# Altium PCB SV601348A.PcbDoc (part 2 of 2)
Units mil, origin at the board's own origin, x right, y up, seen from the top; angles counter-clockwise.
Board outline 3650 x 3650 mil, 6 copper layers (Top Layer, MidLayer1, MidLayer2, MidLayer3, MidLayer4, Bottom Layer), stack 60.8 mil thick; 120 components, 45 nets, 333 pads, 436 vias.
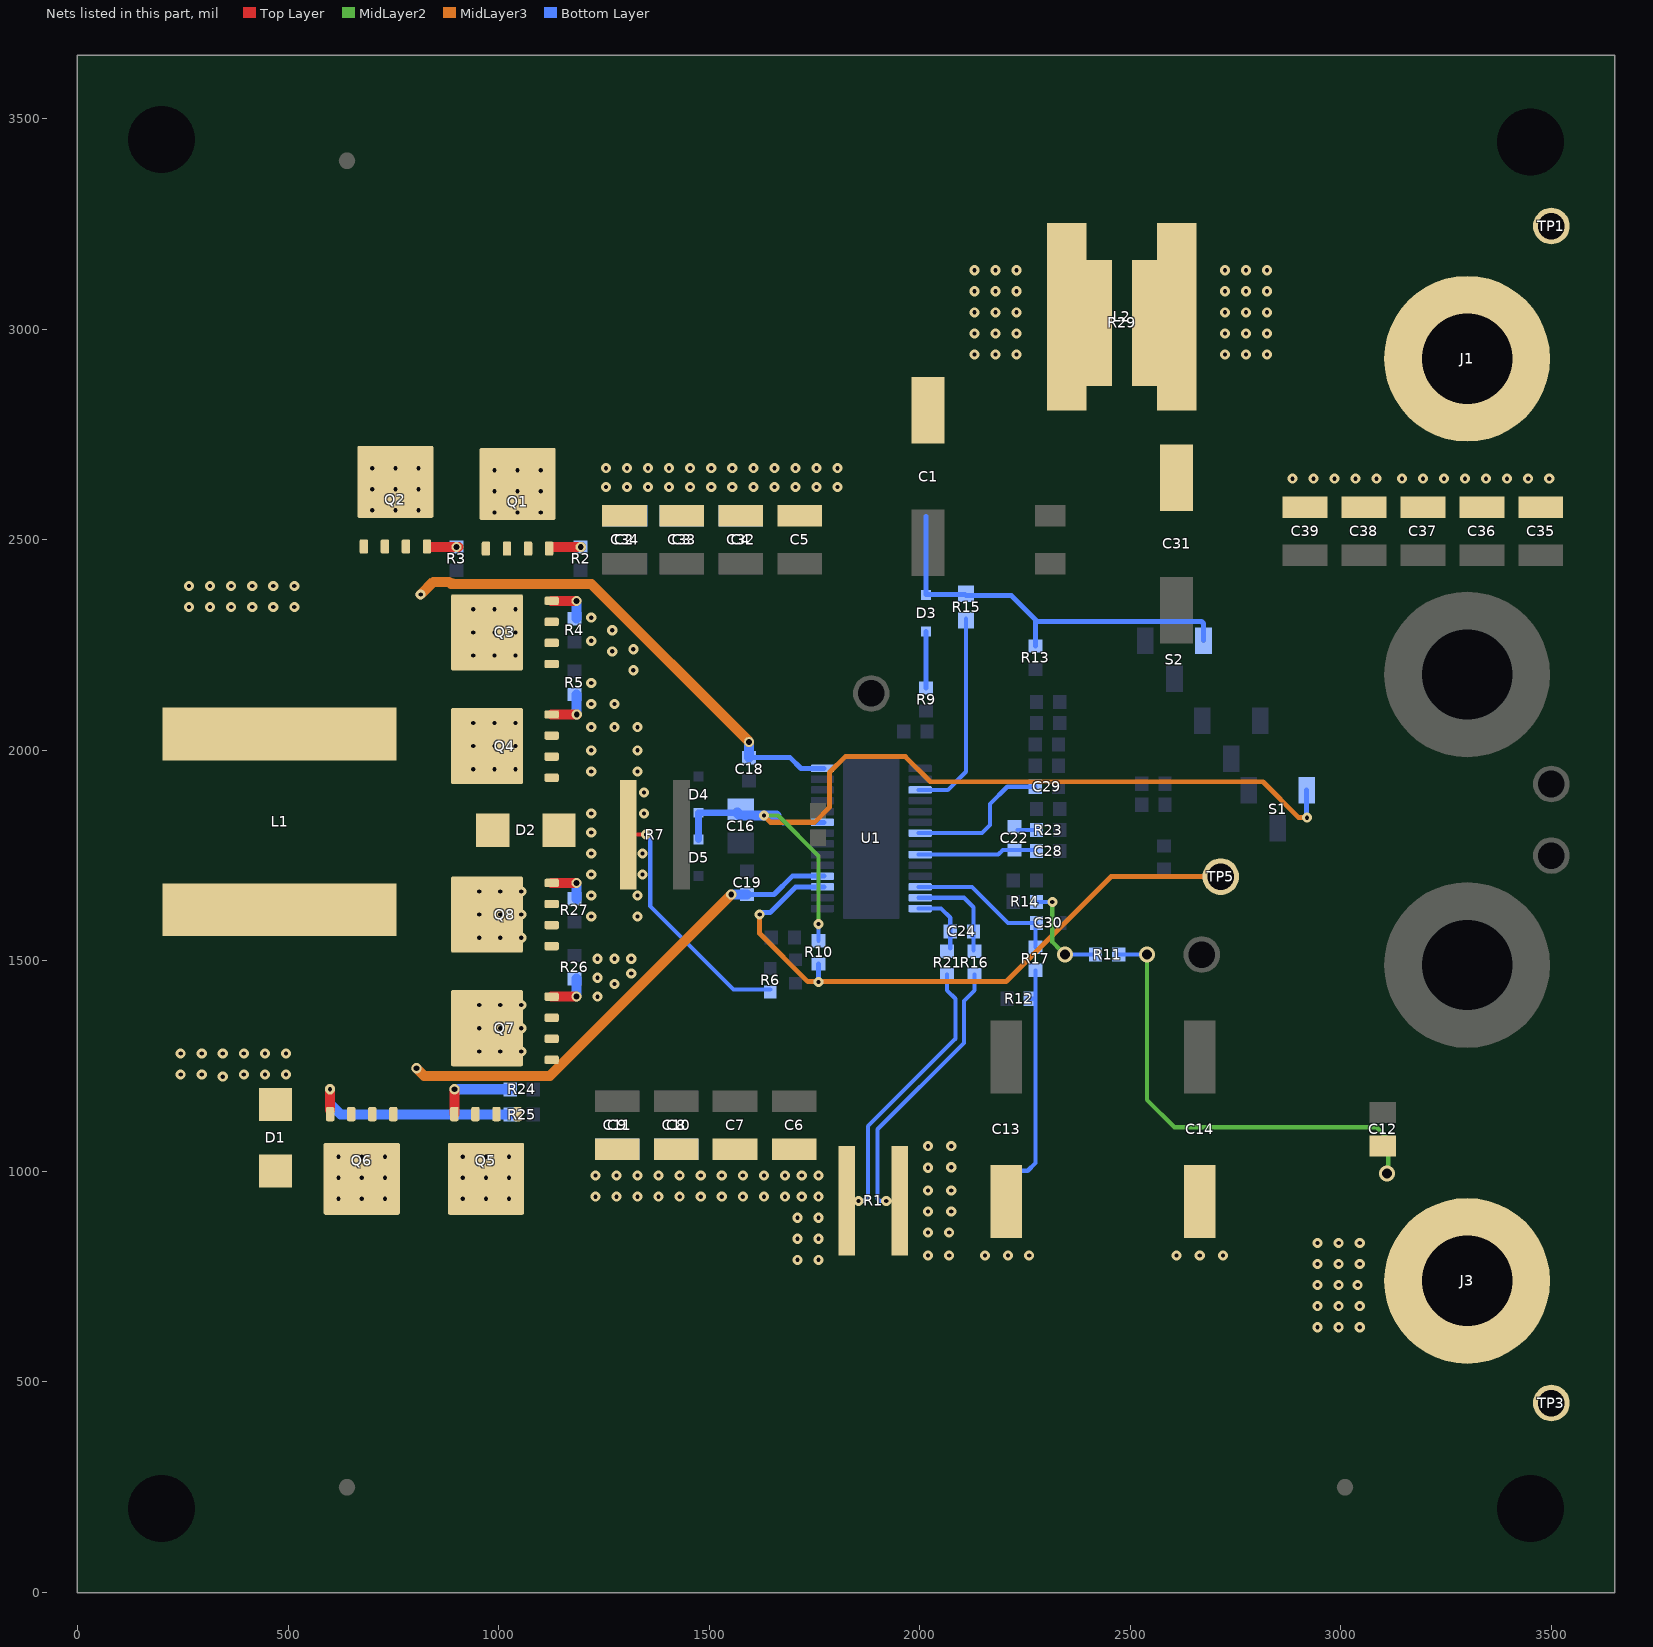
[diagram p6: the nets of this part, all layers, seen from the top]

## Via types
v1: diameter 24, hole 10, Top Layer to Bottom Layer, tented both sides, 317 vias
v2: diameter 24, hole 10, Top Layer to Bottom Layer, 74 vias
v3: diameter 19.68, hole 7.87, Top Layer to Bottom Layer, tented both sides, 12 vias
v4: diameter 24, hole 14, Top Layer to Bottom Layer, 11 vias
v5: diameter 19.68, hole 7.87, Top Layer to Bottom Layer, 9 vias
v6: diameter 24, hole 14, Top Layer to Bottom Layer, tented both sides, 8 vias
v7: diameter 24, hole 10, Top Layer to Bottom Layer, tented top, 2 vias
v8: diameter 38, hole 24, Top Layer to Bottom Layer, 2 vias
v9: diameter 38, hole 24, Top Layer to Bottom Layer, tented both sides, 1 vias

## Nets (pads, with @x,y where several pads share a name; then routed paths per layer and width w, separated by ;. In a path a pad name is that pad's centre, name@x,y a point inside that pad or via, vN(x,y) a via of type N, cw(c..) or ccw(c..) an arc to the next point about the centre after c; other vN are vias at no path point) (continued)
NetC22_1: C22.1 C28.1 U1.9 | length 282.3
  Bottom Layer w10: U1.9@1997.2,1752.24 2186.61,1752.24 2197.44,1763.07 C22.1@2225,1763.07 C28.1@2275,1763.07
NetC22_2: C22.2 R23.2 | length 44.9
  Bottom Layer w10: C22.2@2232.56,1810.63 R23.2@2277.44,1810.63
NetC24_1: C24.1 R16.1 U1.13 | length 242.1
  Bottom Layer w10: U1.13@1997.2,1649.88 2105.12,1649.88 2127.56,1627.44 C24.1@2127.56,1570 R16.1@2127.56,1525
NetC24_2: C24.2 R21.1 U1.14 | length 156.8
  Bottom Layer w10: U1.14@1997.2,1624.29 2050.71,1624.29 2072.44,1602.56 C24.2@2072.44,1570 R21.1@2072.44,1530
NetC29_1: C29.1 U1.7 | length 352.3
  Bottom Layer w10: U1.7@1997.2,1803.43 2147.8,1803.43 2167.13,1822.76 2167.13,1872.76 2207.8,1913.43 C29.1@2274.64,1913.43
NetC31_1: C31.1 C35.1 C36.1 C37.1 C38.1 C39.1 J1.1 L2.1 R29.1 TP1.1
  other v1: 2885,2645 2935,2645 2985,2645 3035,2645 3085,2645 3145,2645 3195,2645 3245,2645 3295,2645 3345,2645 3395,2645 3445,2645 3495,2645 2725,2940 2775,2940 2825,2940 2725,2990 2775,2990 2825,2990 2725,3040 2775,3040 2825,3040 2725,3090 2775,3090 2825,3090 2725,3140 2775,3140 2825,3140
NetD2_2: D2.2 Q3.1 Q3.2 Q3.3 Q4.1 Q4.2 Q4.3 Q7.1 Q7.2 Q7.3 Q8.1 Q8.2 Q8.3 R6.2 R7.2 | length 583
  Top Layer w10: R7.2@1308.37,1799.47 1308.9,1800 v1(1350,1800)
  Bottom Layer w10: v1(1350,1800) 1360,1790 1360,1630 1558,1432 R6.2@1645,1432
  other v1: 1235,1415 1275,1445 1235,1460 1315,1470 1235,1505 1275,1505 1315,1505 1220,1605 1330,1605 1220,1655 1330,1655 1220,1705 1342,1705 1220,1755 1342,1755 1220,1805 1220,1850 1345,1850 1345,1900 1220,1950 1330,1950 1220,2000 1330,2000 1220,2055 1275,2055 1330,2055 1220,2110 1275,2110 1220,2160 1320,2190 1270,2235 1320,2240 1220,2260 1270,2285 1220,2315
NetD3_1: D3.1 R9.2 | length 133.5
  Bottom Layer w12: R9.2@2015,2148.19 D3.1@2015,2281.69
NetQ1_4: Q1.4 R2.1 | length 70.7
  Top Layer w24: Q1.4@1124.27,2483.05 v4(1195,2483.05)
NetQ2_4: Q2.4 R3.1 | length 68.8
  Top Layer w24: Q2.4@836.22,2482.56 v4(900,2482.56) v4@905,2482.56
NetQ3_4: Q3.4 R4.1 | length 101.2
  Top Layer w24: Q3.4@1126.22,2355 v4(1185,2355)
  Bottom Layer w24: R4.1@1185,2312.56 v4(1185,2355)
NetQ4_4: Q4.4 R5.1 | length 106.2
  Top Layer w24: Q4.4@1126.22,2085 v4(1185.55,2085)
  Bottom Layer w24: v4@1185,2085.55 R5.1@1185,2132.44
NetQ5_4: Q5.4 R24.1 | length 191.2
  Top Layer w24: Q5.4@895,1136.22 v4(895,1195)
  Bottom Layer w24: v4(895,1195) R24.1@1027.44,1195
NetQ6_4: Q6.4 R25.1 | length 521.6
  Top Layer w24: Q6.4@600,1146.22 v2(600,1195)
  Bottom Layer w24: v2(600,1195) 600,1160 625,1135 R25.1@1027.44,1135
NetQ7_4: Q7.4 R26.1 | length 101.2
  Top Layer w24: Q7.4@1126.22,1415 v4(1185,1415)
  Bottom Layer w24: v4(1185,1415) R26.1@1185,1457.44
NetQ8_4: Q8.4 R27.1 | length 96.2
  Top Layer w24: Q8.4@1126.22,1685 v4(1185,1685)
  Bottom Layer w24: R27.1@1185,1647.56 v4(1185,1685)
NetR10_1: R10.1 TP5.1 U1.17 | length 1513.1
  MidLayer3 w12: v1(1620,1610) 1620,1565 1734.36,1450.64 2205.08,1450.64 2454.45,1700 TP5.1@2715,1700 TP5.1@2715.13,1700
  Bottom Layer w12: v1(1620,1610) 1625,1615 1645,1615 1705.47,1675.47 U1.17@1772.8,1675.47 ; v1(1760,1450) R10.1@1760,1492.44
NetR11_2: R11.2 R14.2 | length 228.2
  MidLayer2 w10: v7(2315,1640) 2315,1545 v8@2335,1525
  Bottom Layer w10: R14.2@2277.56,1640 v7(2315,1640) ; v8(2345,1515) R11.2@2412.44,1515
NetR15_1: R15.1 U1.3 | length 494.2
  Bottom Layer w10: U1.3@1997.2,1905.79 2066.85,1905.79 2110,1948.94 R15.1@2110,2312.44
SW1: C18.1 D2.1 L1.1 Q1.1 Q1.2 Q1.3 Q2.1 Q2.2 Q2.3 Q3.5 Q3.6 Q3.7 Q3.8 Q3.9@972.48,2280 Q4.5 Q4.6 Q4.7 Q4.8 Q4.9@972.48,2010 U1.28 | length 1175.7
  MidLayer3 w24: v2(815,2370) 845,2400 882.36,2400 886.8,2395.57 891.3,2395.57 891.8,2395.07 1219.93,2395.07 v6(1595,2020)
  Bottom Layer w12: C18.1@1595,1982.56 1692.44,1982.56 1718.03,1956.97 U1.28@1772.8,1956.97
  Bottom Layer w24: C18.1@1595,1982.56 v6(1595,2020)
  other v1: 265,2340 315,2340 365,2340 415,2340 465,2340 515,2340 265,2390 315,2390 365,2390 415,2390 465,2390 515,2390
  other v2: 940,1955 990,1955 1040,1955 940,2010 990,2010 1040,2010 940,2065 990,2065 1040,2065 940,2225 990,2225 1040,2225 940,2280 990,2280 1040,2280 940,2335 990,2335 1040,2335
SW2: C19.2 D1.2 L1.2 Q5.1 Q5.2 Q5.3 Q6.1 Q6.2 Q6.3 Q7.5 Q7.6 Q7.7 Q7.8 Q7.9@972.48,1340 Q8.5 Q8.6 Q8.7 Q8.8 Q8.9@972.48,1610 U1.18 | length 1171.7
  MidLayer3 w24: v4(805,1245) 823.13,1226.87 1121.87,1226.87 v6(1552.44,1657.44)
  Bottom Layer w12: C19.2@1590,1657.44 1654.03,1657.44 1697.65,1701.06 U1.18@1772.8,1701.06
  Bottom Layer w24: v6(1552.44,1657.44) C19.2@1590,1657.44
  other v1: 345,1225 245,1230 295,1230 395,1230 445,1230 495,1230 245,1280 295,1280 345,1280 395,1280 445,1280 495,1280
  other v2: 954,1285 1004,1285 1054,1285 954,1340 1004,1340 1054,1340 954,1395 1004,1395 1054,1395 954,1555 1004,1555 1054,1555 954,1610 1004,1610 1054,1610 954,1665 1004,1665 1054,1665
VCC: C16.2 D4.2 D5.2 R10.2 S1.3 U1.23 | length 2275.6
  MidLayer2 w10: v1(1630,1845) 1664.13,1845 1760,1749.13 v1(1760,1587.87) v1@1760,1580
  MidLayer3 w12: v1(1630,1845) 1645.87,1829.13 1750.47,1829.13 1785.88,1864.54 1785.88,1947.6 1823.29,1985 1965.8,1985 2025,1925.8 2815,1925 2900,1840 v1(2920,1840)
  Bottom Layer w10: R10.2@1760,1547.56 v1@1760,1580
  Bottom Layer w12: 1675.98,1829.02 U1.23@1768.86,1829.02 U1.23@1772.8,1829.02 ; v1@2918.9,1841.1 S1.3@2918.9,1905.28
  Bottom Layer w16: D5.2@1475,1788.31 D4.2@1475,1851.69 C16.2@1566.69,1851.69 ; 1659.41,1845.59 1675.98,1829.02
  Bottom Layer w24: C16.2@1566.69,1851.69 1572.79,1845.59 1659.41,1845.59
VIN: C1.1 C2.1 C3.1 C4.1 C5.1 C32.1 C33.1 C34.1 D3.2 L2.2 Q1.5 Q1.6 Q1.7 Q1.8 Q1.9@1045,2632.52 Q2.5 Q2.6 Q2.7 Q2.8 Q2.9@755,2637.52 R13.2 R15.2 R29.2 S2.3 | length 973.3
  Bottom Layer w12: 2015,2555 2015,2369.47 R15.2@2108.09,2369.47 ; R15.2@2110,2367.56 2217.44,2367.56 2275,2310 ; R13.2@2275,2247.56 2275,2250 2275,2310 ; S2.3@2673.9,2260.28 2673.9,2301.1 2669.35,2305.65 2279.35,2305.65 2275,2310
  other v1: 1255,2625 1305,2625 1355,2625 1405,2625 1455,2625 1505,2625 1555,2625 1605,2625 1655,2625 1705,2625 1755,2625 1805,2625 1255,2670 1305,2670 1355,2670 1405,2670 1455,2670 1505,2670 1555,2670 1605,2670 1655,2670 1705,2670 1755,2670 1805,2670 2130,2940 2180,2940 2230,2940 2130,2990 2180,2990 2230,2990 2130,3040 2180,3040 2230,3040 2130,3090 2180,3090 2230,3090 2130,3140 2180,3140 2230,3140
  other v2: 990,2565 1045,2565 1100,2565 700,2570 755,2570 810,2570 990,2615 1045,2615 1100,2615 700,2620 755,2620 810,2620 990,2665 1045,2665 1100,2665 700,2670 755,2670 810,2670
VOSNS: C30.1 R17.2 U1.12 | length 370.6
  Bottom Layer w10: U1.12@1997.2,1675.47 2124.53,1675.47 2210,1590 C30.1@2277.44,1590 ; R17.2@2275,1532.56 C30.1@2275,1587.56
VOSNS+: C6.1 C7.1 C8.1 C9.1 C10.1 C11.1 D1.1 Q5.5 Q5.6 Q5.7 Q5.8 Q5.9@970,982.48 Q6.5 Q6.6 Q6.7 Q6.8 Q6.9@675,982.48 R1.1 R21.2 | length 648.1
  Bottom Layer w10: v1(1855,930) 1867.13,930 1877.13,940 1877.13,1107.4 2085,1315.28 2085,1410 2065,1430 R21.2@2065,1467.44
  other v1: 1710,790 1760,790 1710,840 1760,840 1710,890 1760,890 1230,940 1280,940 1330,940 1380,940 1430,940 1480,940 1530,940 1580,940 1630,940 1680,940 1720,940 1760,940 1230,990 1280,990 1330,990 1380,990 1430,990 1480,990 1530,990 1580,990 1630,990 1680,990 1720,990 1760,990
  other v2: 620,935 675,935 730,935 915,935 970,935 1025,935 620,985 675,985 730,985 915,985 970,985 1025,985 620,1035 675,1035 730,1035 915,1035 970,1035 1025,1035
VOSNS-: C12.1 C13.1 C14.1 J3.1 R1.2 R11.1 R12.1 R16.2 R17.1 TP3.1 | length 2300.6
  MidLayer2 w10: v8(2540,1515) 2540,1170 2605,1105 3085,1105 3112.5,1077.5 v9@3112.5,997.5
  Bottom Layer w10: v1(1920.51,930) 1905,930 1900,935 1900,1100 2105,1305 2105,1405 2130,1430 R16.2@2130,1467.44 ; 2210,1001.57 2256.57,1001.57 2275,1020 R12.1@2275,1410 ; R12.1@2262.56,1410 R12.1@2275,1410 ; R17.1@2275,1477.44 R12.1@2275,1410 ; R11.1@2468.05,1515 R11.1@2472.56,1515 v8(2540,1515)
  other v1: 2945,630 2995,630 3045,630 2945,680 2995,680 3045,680 2945,730 2995,730 3040,730 2945,780 2995,780 3045,780 2020,800 2070,800 2155,800 2210,800 2260,800 2610,800 2665,800 2720,800 2945,830 2995,830 3045,830 2020,855 2070,855 2020,905 2075,905 2020,955 2075,955 2019.64,1008.59 2075,1010 2020,1060 2075,1060
  other v9: 3110,995
pads on no net: FID1.1 FID2.1 FID3.1 H5.0 H6.0 H7.0 H8.0 LBL1.0 MH1.1 MH2.1 MH3.1 MH4.1 Q1.9@987.13,2582.91 Q1.9@987.13,2649.06 Q1.9@1045,2582.91 Q1.9@1045,2649.06 Q1.9@1102.87,2582.91 Q1.9@1102.87,2649.06 Q2.9@697.13,2587.91 Q2.9@697.13,2654.06 Q2.9@755,2587.91 Q2.9@755,2654.06 Q2.9@812.87,2587.91 Q2.9@812.87,2654.06 Q3.9@955.94,2222.13 Q3.9@955.94,2280 Q3.9@955.94,2337.87 Q3.9@1022.09,2222.13 Q3.9@1022.09,2280 Q3.9@1022.09,2337.87 Q4.9@955.94,1952.13 Q4.9@955.94,2010 Q4.9@955.94,2067.87 Q4.9@1022.09,1952.13 Q4.9@1022.09,2010 Q4.9@1022.09,2067.87 Q5.9@912.13,965.94 Q5.9@912.13,1032.09 Q5.9@970,965.94 Q5.9@970,1032.09 Q5.9@1027.87,965.94 Q5.9@1027.87,1032.09 Q6.9@617.13,965.94 Q6.9@617.13,1032.09 Q6.9@675,965.94 Q6.9@675,1032.09 Q6.9@732.87,965.94 Q6.9@732.87,1032.09 Q7.9@955.94,1282.13 Q7.9@955.94,1340 Q7.9@955.94,1397.87 Q7.9@1022.09,1282.13 Q7.9@1022.09,1340 Q7.9@1022.09,1397.87 Q8.9@955.94,1552.13 Q8.9@955.94,1610 Q8.9@955.94,1667.87 Q8.9@1022.09,1552.13 Q8.9@1022.09,1610 Q8.9@1022.09,1667.87 S3.3 U1.29@1885,1790.63

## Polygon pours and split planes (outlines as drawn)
GND on MidLayer3 "Top Layer-No Net 6" (solid, remove dead copper, pour order 69): 0,15 0,3650 3650,3650 3650,15
GND on MidLayer4 "Top Layer-No Net 6" (solid, remove dead copper, pour order 70): 0,20 0,3650 3630,3650 3630,20
GND on MidLayer1 "Top Layer-No Net 6" (solid, remove dead copper, pour order 61): 0,20 0,3630 3630,3630 3630,20
GND on MidLayer2 "M4 3D STEP Bottom-No Net" (solid, remove dead copper, pour order 68): 1215.67,2500 3565,2500 3650,2415 3650,1955 3550,1855 3150.67,1855 3150.67,1825 3555,1825 3650,1730 3650,1105 1195.67,1105 1195.67,1195 1375.64,1374.97 1375.64,1524.4 1377.24,1800 1375.71,2065.59 1375.67,2245 1215.67,2405
SW2 on MidLayer2 "Top Layer-No Net 3" (solid, remove dead copper, pour order 63): 1085.08,1110 285,1110 195,1200 195,1640 720,1640 815,1735 1079.88,1735
SW1 on MidLayer2 "Top Layer-No Net 4" (solid, remove dead copper, pour order 64): 1080,1765 1080,2510 265.4,2510 194.3,2439.6 192.24,2233.86 192.24,1990 715,1990 940,1765
NetD2_2 on MidLayer2 "Top Overlay-No Net" (solid, remove dead copper, pour order 62): 1102.7,1221.89 1104.59,1220 1195,1220 1365,1390 1365,1775 1299.71,1775 1299.71,1825 1365,1825 1365,2240 1205,2400 1102.7,2400
VIN on MidLayer2 "Top Layer-No Net 2" (solid, remove dead copper, pour order 67): 2288.74,2525 135,2525 0,2660 0,3145 130,3275 2376.22,3275 2400,3251.22 2400,2636.26
VOSNS- on MidLayer2 "Top Layer-No Net 1" (solid, remove dead copper, pour order 66): 3505,355 2015,355 1915,455 1915,1070 1935,1090 3540,1090 3650,980 3650,500
VOSNS+ on MidLayer2 "Top Layer-No Net" (solid, remove dead copper, pour order 65): 1865,1065 1865,445 1775,355 105,355 0,460 0,985 105,1090 1840,1090
NetC31_1 on Bottom Layer "Bottom Layer -InFltr" (solid, pour order 80): 3550,2550 2585,2550 2560,2575 2560,3265 2605,3310 3565,3310 3650,3225 3650,2650
GND on Bottom Layer "Bottom Layer-No Net 1" (solid, remove dead copper, pour order 79): 3650,2410 3650,1955 3550,1855 3140.56,1855 3140.56,1824.63 3555.37,1824.63 3650,1730 3650,1225 3535.63,1110.63 1199.28,1110.63 1185.56,1124.35 1185.56,1200.63 1365.53,1380.61 1367.79,1382.87 1367.79,1766.27 1367.79,1767.87 1375.56,1775.63 1416.25,1775.63 1416.25,1824.63 1372.64,1824.63 1369.11,1828.17 1367.79,1829.48 1367.79,2240.63 1367.79,2248.39 1205.56,2410.63 1210.36,2415.44 1210.36,2485.59 1230.41,2505.63 3554.37,2505.63
NetD2_2 on Bottom Layer "Top Overlay-No Net" (solid, remove dead copper, pour order 72): 1105,1221.89 1106.89,1220 1197.3,1220 1367.3,1390 1367.3,2240 1207.3,2400 1105,2400
GND on Bottom Layer "Top Layer-No Net 5" (solid, remove dead copper, pour order 71): 2545,2190 2545,1560.63 2254.33,1552.24 2257.76,1739.96 2315,1739.96 2315,2190
VOSNS+ on Bottom Layer "Top Layer-No Net" (solid, remove dead copper, pour order 75): 1865,1080 1865,445 1775,355 105,355 0,460 0,980 110,1090 1855,1090
VOSNS- on Bottom Layer "Top Layer-No Net 1" (solid, remove dead copper, pour order 76): 3500,350 2025,350 1915,460 1915,1080 1925,1090 3540,1090 3650,980 3650,500
VIN on Bottom Layer "Top Layer-No Net 2" (solid, remove dead copper, pour order 77): 2289.36,2524.36 135.64,2524.36 0,2660 0,3145 129.36,3274.36 2377.92,3274.36 2400,3252.28 2400,2635
SW1 on Bottom Layer "Top Layer-No Net 4" (solid, remove dead copper, pour order 74): 1080,1785 1080,2500 1070,2510 265,2510 195,2440 195,2040 245,1990 715,1990 940,1765 1060,1765
SW2 on Bottom Layer "Top Layer-No Net 3" (solid, remove dead copper, pour order 73): 954.8,1110 285,1110 194.92,1200.08 194.92,1589.92 245,1640 719.92,1640 814.92,1735 1060,1735 1085,1710 1085,1241.29
NetC31_1 on Top Layer "Top Layer -InFltr" (solid, pour order 78): 3550,2550 2585,2550 2560,2575 2560,3265 2605,3310 3565,3310 3650,3225 3650,2650
NetD2_2 on Top Layer "Top Overlay-No Net" (solid, remove dead copper, pour order 54): 1102.7,1221.89 1104.59,1220 1195,1220 1365,1390 1365,2240 1205,2400 1102.7,2400
SW2 on Top Layer "Top Layer-No Net 3" (solid, remove dead copper, pour order 55): 1051.88,1110 285,1110 195,1200 195,1680 205,1690 770,1690 815,1735 1060,1735 1085,1710 1085,1143.4
SW1 on Top Layer "Top Layer-No Net 4" (solid, remove dead copper, pour order 56): 1080,1785 1080,2500 1070,2510 265.4,2510 194.3,2439.6 192.24,2233.86 192.24,1982.76 205,1970 735,1970 940,1765 1060,1765
VOSNS+ on Top Layer "Top Layer-No Net" (solid, remove dead copper, pour order 57): 1865,1080 1865,445 1775,355 105,355 0,460 0,980 110,1090 1855,1090
GND on Top Layer "M4 3D STEP Bottom-No Net" (solid, remove dead copper, pour order 60): 1240,2505 3560,2505 3650,2415 3650,1955 3545,1850 3150,1850 3150,1825 3555,1825 3650,1730 3650,1225 3535,1110 1199.91,1110 1185,1124.91 1185,1190 1374.97,1379.97 1374.97,1529.4 1375.04,2070.59 1375,2250 1215,2410 1215,2480
VOSNS- on Top Layer "Top Layer-No Net 1" (solid, remove dead copper, pour order 58): 3502.01,355 2020,355 1915,460 1915,1080 1925,1090 3540,1090 3650,980 3650,502.99
VIN on Top Layer "Top Layer-No Net 2" (solid, remove dead copper, pour order 59): 2290,2525 135,2525 0,2660 0,3145 130,3275 2377.28,3275 2400,3252.28 2400,2635

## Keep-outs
Keep-Out Layer:
  the board outline again, w7
  text ".Layer_Name" at 377,-858.49 h60

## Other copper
Top Layer:
  pour cut-out: 1901.81,799.09 1878.19,799.09 1878.19,1061.89 1901.81,1061.89
  pour cut-out: 3627.38,1825 3152.62,1825 3152.62,1855 3627.38,1855
  pour cut-out: 1435,1775 1385,1775 1380,1770 1375,1765.64 1362.77,1765.64 1355,1775 1295,1775 1295,1825 1296,1824 1355,1825 1362.76,1831.07 1375.01,1831.08 1382.08,1824 1435,1824
  text ".Layer_Name" at 377,-858.49 h60
MidLayer1:
  pour cut-out: 1374.36,1825.53 1402.13,1825.53 1410,1817.66 1410,1783.3 1402.34,1775.53 1374.36,1775.53
  pour cut-out: 3624.76,1825 3150,1825 3150,1855 3624.76,1855
  text ".layer_Name" at 375,-860 h60
MidLayer2:
  pour cut-out: 3624.76,1825 3150,1825 3150,1855 3624.76,1855
  pour cut-out: 1875,910 1845,910 1835,920 1835,940 1845,950 1875,950
  pour cut-out: 1905,950 1935,950 1945,940 1945,920 1935,910 1905,910
  pour cut-out: 1374.36,1825.53 1402.13,1825.53 1410,1817.66 1410,1783.3 1402.34,1775.53 1374.36,1775.53
  text ".layer_Name" at 375,-860 h60
MidLayer3:
  pour cut-out: 3624.76,1825 3150,1825 3150,1855 3624.76,1855
  pour cut-out: 1374.36,1824.47 1402.13,1824.47 1410,1816.6 1410,1782.24 1402.34,1774.47 1374.36,1774.47
  text ".layer_Name" at 375,-860 h60
MidLayer4:
  rectangle net SW2: 885,1239.61 1090,1705
  rectangle net SW1: 890,1915 1095,2380.39
  pour cut-out: 1374.36,1824.47 1402.13,1824.47 1410,1816.6 1410,1782.24 1402.34,1774.47 1374.36,1774.47
  pour cut-out: 3627.06,1824.41 3152.31,1825.67 3152.31,1855 3627.06,1855
  pour cut-out: 1365,1780 1335,1780 1325,1790 1325,1810 1335,1820 1365,1820
  text ".layer_Name" at 375,-860 h60
Bottom Layer:
  pour cut-out: 2645,2030 2700,2030 2700,2110 2645,2110
  pour cut-out: 2505,2225 2565,2225 2565,2295 2505,2295
  pour cut-out: 2755,1865 2810,1865 2810,1945 2755,1945
  pour cut-out: 1365,1780 1335,1780 1325,1790 1325,1810 1335,1820 1365,1820
  pour cut-out: 1875,910 1845,910 1835,920 1835,940 1845,950 1875,950
  pour cut-out: 1900,950 1930,950 1940,940 1940,920 1930,910 1900,910
  pour cut-out: 1374.36,1824.52 1402.13,1824.52 1410,1816.65 1410,1782.29 1402.34,1774.52 1374.36,1774.52
  pour cut-out: 3627.06,1825 3152.31,1825 3152.31,1855 3627.06,1855
  pour cut-out: 1681.38,1470 1728.62,1470 1728.62,1411.38 1723,1417 1683.01,1417
  pour cut-out: 1350,1800 1350,1620 1365,1605 1365,1800
  text ".Layer_Name" at 377,-858.49 h60

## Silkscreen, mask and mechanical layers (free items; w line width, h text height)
Top Overlay:
  region: 2085,3070 1785,3070 1785,2970 2085,2970
  text "VIN" at 3045,3310 h70
  text "6-36VDC" at 2770,3195 h70
  text ".PRJ_Number" at 1125,2990 h60
  text ".PCB_Rev" at 1605,2990 h60
  text "-" at 1725,2990 h60
  text "+" at 3530,2885 h120
  text "-" at 3530,2115 h120
  text "-" at 3530,1445 h120
  text "+" at 3530,670 h120
  text "VOUT" at 2860,515 h70
  text "12VDC" at 2835,380 h70
  text ".Layer_Name" at 377,-858.49 h60
Bottom Overlay:
  lines w7: 1590,1505 1590,1520 1615,1545 ; 2835,1755 2790,1755 2770,1775 ; 1615,1545 1615,1530 1600,1545 1615,1545 ; 2770,1775 2770,1760 2785,1775 2770,1775
  text "EN" at 2725,2305 h40
  text "OFF" at 2470,2295 h40 r90
  text "ON" at 2795,2290 h40 r90
  text "DITH" at 2920,2125 h40
  text "OFF" at 2605,2075 h40 r90
  text "MODE" at 3110,1955 h40
  text "CCM" at 3040,1925 h40 r90
  text "DCM" at 2965,1720 h40
  text ".Layer_Name" at 377,-858.49 h60
Top Paste:
  text ".Layer_Name" at 377,-858.49 h60
Bottom Paste:
  text ".Layer_Name" at 377,-858.49 h60
Top Solder:
  text ".Layer_Name" at 377,-858.49 h60
  text ".Layer_Name" at 377,-858.49 h60
Bottom Solder:
  text ".Layer_Name" at 377,-858.49 h60
Drill Guide:
  text ".Layer_Name" at 377,-858.49 h60
M1 Board Outline:
  the board outline again, w8
  text ".Layer_Name" at 377,-858.49 h60
M2 Board Dimensions:
  rectangle: -200,-285.5 -75,-160.5
  rectangle: -75,-410.5 300,-285.5
  lines w7: -200,-285.5 800,-285.5 ; -75,-410.5 -75,-160.5 ; 50,-410.5 50,-160.5 ; 300,-410.5 300,-160.5 ; 550,-410.5 550,-160.5 ; -200,-410.5 800,-410.5 800,-160.5 -200,-160.5 -200,-410.5
  text ".Layer_Name" at 377,-858.49 h60
M3 3D STEP Top:
  text ".Layer_Name" at 377,-858.49 h60
M4 3D STEP Bottom:
  text ".Layer_Name" at 377,-858.49 h60
M5 Assembly Top:
  lines w10: -492,-930.17 6108,-930.17 ; -492,-726.83 6110,-726.83 ; -492,-523.5 -492,-1133.5 3513,-1133.5 6110,-1133.5 6110,-523.5 -491.5,-523.5 -491.5,-1133.5 1084,-1133.5 ; 1973,-1133.5 1973,-523.5 ; 3240,-726.83 3240,-523.5 ; 4080,-726.83 4080,-523.5 ; 4702,-1140 4702,-937.17
  text "NOTE: / -001 Install L2 only / -002 Install R29 only" at 2105,3735 h40
  text "COMPONENTS MARKED 'DNP' SHOULD NOT BE POPULATED." at 953.5,-318.5 h60
  text "ASSEMBLY VARIANT:" at 953,-434 h60
  text ".VariantName" at 1989,-434 h60
  text "PCB VIEWED FROM TOP SIDE" at -428.5,-655.67 h60
  text "BOARD #:" at 2048,-655.67 h60
  text ".PRJ_Number" at 2593.5,-655.67 h60
  text "REV:" at 3438,-655.67 h60
  text ".PCB_Rev" at 3729.5,-655.67 h60
  text "SVN REV:" at 4276,-655.67 h60
  text ".VersionControl_RevNumber" at 4782,-655.67 h60
  text "IGNORE ->" at -428.5,-858.49 h60
  text "PLOT NAME =" at -428.5,-1064.34 h60
  text ".plot_File_Name" at 377,-1064.34 h60
  text "GENERATED    :" at 2050,-1064.34 h60
  text ".Print_Date" at 2919.5,-1064.34 h60
  text ".Print_Time" at 3648.5,-1064.34 h60
  text "TEXAS INSTRUMENTS" at 4913,-1064.34 h60
M6 Assembly Bottom:
  lines w10: -492.5,-727.33 6109.5,-727.33 ; -490.5,-930.67 6109.5,-930.67 ; 915.5,-1140.5 915.5,-937.67 ; 1537.5,-727.33 1537.5,-524 ; 2377.5,-727.33 2377.5,-524 ; 3644.5,-1134 3644.5,-524 ; 4533.5,-1134 6109,-1134 6109,-524 -492.5,-524 -492.5,-1134 2104.5,-1134 6109.5,-1134 6109.5,-524
  text "COMPONENTS MARKED 'DNP' SHOULD NOT BE POPULATED." at 5902,-318 h60
  text ".VariantName" at 4858,-434 h60
  text "ASSEMBLY VARIANT:" at 5897,-434 h60
  text ".VersionControl_RevNumber" at 835.5,-656.17 h60
  text "SVN REV:" at 1341.5,-656.17 h60
  text ".PCB_Rev" at 1888,-656.17 h60
  text "REV:" at 2179.5,-656.17 h60
  text ".PRJ_Number" at 3024,-656.17 h60
  text "BOARD #:" at 3569.5,-656.17 h60
  text "PCB VIEWED FROM BOTTOM SIDE" at 6046,-656.17 h60
  text "IGNORE ->" at 2347.85,-858.49 h60
  text "TEXAS INSTRUMENTS" at 704.5,-1064.84 h60
  text ".Print_Time" at 1969,-1064.84 h60
  text ".Print_Date" at 2698,-1064.84 h60
  text "GENERATED    :" at 3567.5,-1064.84 h60
  text ".plot_File_Name" at 5240.5,-1064.84 h60
  text "PLOT NAME =" at 6046,-1064.84 h60
M9 Title Sheet:
  lines w10: -691.5,1041.5 -491.5,1041.5 ; -691.5,3416.5 -491.5,3416.5 ; -691.5,5791.5 -491.5,5791.5 ; 1808.5,-1333.5 1808.5,-1133.5 ; 1808.5,7966.5 1808.5,8166.5 ; 4308.5,-1333.5 4308.5,-1133.5 ; 4308.5,7966.5 4308.5,8166.5 ; 6121,-1133.5 6121,-523.5 11103.5,-523.5 ; 6808.5,-1333.5 6808.5,-1133.5 ; 6808.5,7966.5 6808.5,8166.5 ; 9308.5,-1333.5 9308.5,-1133.5 ; 9308.5,7966.5 9308.5,8166.5 ; 11103.5,-1133.5 11103.5,-523.5 ; 11103.5,-823.5 14103.5,-823.5 ; 11103.5,-223.5 14103.5,-223.5 ; 11104.5,370.5 14104.5,370.5 ; 11808.5,-1333.5 11808.5,-1133.5 ; 11808.5,7966.5 11808.5,8166.5 ; 12608.5,-1123.5 12608.5,-523.5 ; 14103.5,-523.5 11103.5,-523.5 ; 14103.5,76.5 11103.5,76.5 ; 14108.5,66.5 14108.5,-1133.5 ; 14108.5,871 11104.5,871 11103.5,871 11103.5,370.5 11103.5,76.5 ; 14108.5,1041.5 14308.5,1041.5 ; 14108.5,3416.5 14308.5,3416.5 ; 14108.5,5791.5 14308.5,5791.5 ; 11103.5,-523.5 11103.5,76.5 ; 14108.5,-1133.5 14108.5,7966.5 -491.5,7966.5 -491.5,-1133.5 14108.5,-1133.5 ; -691.5,-1333.5 -691.5,8166.5 14308.5,8166.5 14308.5,-1333.5 -691.5,-1333.5
  text "1" at 539.84,8036.5 h70
  text "2" at 3035.5,8036.5 h70
  text "3" at 5524.84,8036.5 h70
  text "4" at 8031.51,8036.5 h70
  text "5" at 10530.5,8036.5 h70
  text "6" at 13035.5,8036.5 h70
  text "A" at -616.5,6893.5 h70
  text "A" at 14183.5,6893.5 h70
  text "B" at -616.5,4513.5 h70
  text "B" at 14183.5,4513.5 h70
  text "C" at -616.5,2138.5 h70
  text "C" at 14183.5,2138.5 h70
  text "PROJECT TITLE:" at 11143.5,277.5 h45
  text ".PRJ_Title" at 11193.5,144.17 h70
  text "DESIGNED FOR:" at 11143.5,-23.5 h45
  text ".PRJ_Customer" at 11193.5,-163.5 h70
  text "D" at -616.5,-231.5 h70
  text "D" at 14183.5,-231.5 h70
  text "FILE NAME:" at 11143.5,-323.5 h45
  text ".PCB_File_Name_No_Path" at 11193.5,-443.5 h70
  text "ENGINEER:" at 11143.5,-613.5 h45
  text "LAYOUT BY:" at 12648.5,-613.5 h45
  text ".PRJ_Engineer" at 11193.5,-768.49 h70
  text ".PCB_Layout" at 12699,-768.49 h70
  text ".Layer_Name" at 377,-858.49 h60
  text "ALTIUM DESIGNER VERSION:" at 12648.5,-923.5 h45
  text ".print_Scale" at 11193.5,-1056.83 h70
  text ".Application_BuildNumber" at 12699,-1056.83 h70
  text "1" at 539.84,-1263.5 h70
  text "2" at 3035.5,-1263.5 h70
  text "3" at 5524.84,-1263.5 h70
  text "4" at 8031.51,-1263.5 h70
  text "5" at 10530.5,-1263.5 h70
  text "6" at 13035.5,-1263.5 h70
M10 Fab Notes:
  drawing of 185 lines, arcs and shapes, not listed
  text "DESIGN INFORMATION" at 12181.02,5910 h60
  text "MIN. TRACK WIDTH:" at 11536.46,5730 h60
  text "8" at 12632.7,5730 h60
  text "MIL" at 12787.46,5730 h60
  text "MIN. CLEARANCE:" at 11536.46,5598 h60
  text "0.2" at 12572.7,5598 h60
  text "mm" at 12787.46,5598 h60
  text "MIN. VIA PAD SIZE:" at 11536.46,5466 h60
  text "24" at 12602.71,5466 h60
  text "MIL" at 12787.46,5466 h60
  text "0.05mm (2MIL)" at 12231.46,5324.29 h60
  text "MINIMUM ANNULAR RING" at 11207.23,5320 h60
  text "EXTERNAL" at 12939.46,5320 h60
  text "PER" at 11407.23,5202 h60
  text "IPC-D-275 CLASS 2 LEVEL C" at 11627.23,5202 h60
  text "MIL, HOLES" at 13115.46,5089.71 h60
  text "+/-" at 12723,5089 h60
  text "+/-" at 13577,5089 h60
  text "REGISTRATION TOLERANCES:" at 11207.23,5084 h60
  text "METAL" at 12407,5084 h60
  text "5" at 12983.2,5084 h60
  text "3" at 13816.2,5084 h60
  text "MIL" at 13932.46,5084 h60
  text "MATERIAL:" at 11132.46,4874.54 h60
  text "FR-4 High Tg" at 12118.9,4734.21 h60
  text "FR-408" at 11553.46,4725.64 h60
  text "X" at 11965.46,4725.64 h60
  text "OTHER" at 13041.46,4725.64 h60
  text "62 MIL (1.6mm) +/-10%" at 11873.56,4562.92 h60
  text "THICKNESS:" at 11207.23,4558.64 h60
  text "X" at 11745.4,4558.64 h60
  text "OTHER" at 13158.46,4558.64 h60
  text "TOLERANCE:" at 11207.23,4400.64 h60
  text "X" at 12046.53,4400.64 h60
  text "ANSI IPC-6012 TYPE 3 CLASS 2" at 12233.48,4400.64 h60
  text "OTHER +/-" at 12233.46,4244.64 h60
  text "BOW & TWIST:" at 11207.23,4087.64 h60
  text "X" at 12046.53,4087.64 h60
  text "ANSI IPC-6012 TYPE 3 CLASS 2" at 12233.48,4087.64 h60
  text "OTHER +/-" at 12233.46,3929.13 h60
  text "DRILLING:" at 11132.46,3790.64 h60
  text "REFERENCE:" at 11207.23,3673.64 h60
  text "X" at 11855.46,3673.64 h60
  text "AS SHOWN" at 12042.46,3673.64 h60
  text "X" at 12756.46,3673.64 h60
  text "NC_DRILL FILES" at 12893.46,3673.64 h60
  text "PTH MIN COPPER THICKNESS:" at 11207.23,3515.64 h60
  text "X" at 12557.46,3515.64 h60
  text "1MIL" at 12694.46,3515.64 h60
  text "OTHER" at 13191.46,3515.64 h60
  text "BOARD FINISH:" at 11132.46,3356.64 h60
  text "SILKSCREEN:" at 11287.68,3238.64 h60
  text "X" at 12236.46,3238.64 h60
  text "TOP" at 12362.46,3238.64 h60
  text "X" at 12746.46,3238.64 h60
  text "BOTTOM" at 12873.46,3238.64 h60
  text "SILKSCREEN COLOR:" at 11287.68,3071.64 h60
  text "X" at 12235.42,3071.64 h60
  text "WHITE" at 12362.46,3071.64 h60
  text "OTHER" at 12873.46,3071.64 h60
  text "SOLDER RESIST COLOR:" at 11287.68,2901.64 h60
  text "X" at 11855.42,2742.44 h60
  text "GREEN" at 11982.46,2742.44 h60
  text "BLUE" at 12573.46,2742.44 h60
  text "OTHER" at 13111.46,2742.44 h60
  text "IMMERSION GOLD (ENIG)" at 12193.46,2553.92 h60
  text "ENEPIG" at 13531,2550.64 h60
  text "SURFACE FINISH:" at 11132.46,2549.64 h60
  text "X" at 12006.51,2549.64 h60
  text "IMM. TIN/SILVER OR EQUIV" at 11462,2392.64 h60
  text "OTHER" at 12893.46,2392.64 h60
  text "ARRAY/PANEL:" at 11132.46,2213.64 h60
  text "X" at 12000,2210 h60
  text "CUT AND TRIM PER MECH LAYER 1" at 12193.46,2209.35 h60
  text "N.C. ROUTE" at 12193.46,2057.64 h60
  text "V. SCORE" at 13059.46,2057.64 h60
  text "CERTIFICATION:" at 11132.46,1920.64 h60
  text "MATERIALS AND WORKMANSHIP FOR ALL PCBS" at 11857.46,1920.64 h60
  text "TO MEET OR EXCEED THE REQUIREMENTS OF:" at 11857.46,1822.64 h60
  text "X" at 11483.96,1686.13 h60
  text "ANSI IPC-A-600F CLASS ->" at 11622.96,1686.13 h60
  text "X" at 13262.02,1686.13 h60
  text "2" at 13380.96,1686.14 h60
  text "1" at 13065.96,1684.64 h60
  text "3" at 13734.96,1684.64 h60
  text "X" at 11486.02,1526.64 h60
  text "UL 94V-0" at 11622.96,1526.64 h60
  text "X" at 12298.02,1526.64 h60
  text "RoHS" at 12434.96,1526.64 h60
  text "OTHER" at 13079.36,1526.64 h60
  text "PER ORDER" at 13476.42,1526.64 h60
  text "ADDITIONAL REQUIREMENTS:" at 11132.46,1385.64 h60
  text "MICROSECTION:" at 11207.23,1270.64 h60
  text "YES" at 12112.96,1270.64 h60
  text "REQUIRED" at 12974.46,1114.49 h60
  text "BARE BOARD ELEC. TEST:" at 11207.23,1111.64 h60
  text "NONE" at 12512.96,1111.64 h60
  text "X" at 12847.46,1111.64 h60
  text "PER ORDER" at 13566.46,1111.64 h60
  text "MANUFACTURER'S UL:" at 11207.23,954.64 h60
  text "RAIL" at 12372.96,950.35 h60
  text "METAL" at 12864.77,950.35 h60
  text "X" at 13240,950 h60
  text "SILK" at 13376.46,950.35 h60
  text ".Layer_Name" at 377,-858.49 h60
M11 Gerber Information:
  lines w10: -492,-930.17 6108,-930.17 ; -492,-726.83 6110,-726.83 ; -492,-523.5 -492,-1133.5 3513,-1133.5 6110,-1133.5 6110,-523.5 -491.5,-523.5 -491.5,-1133.5 1084,-1133.5 ; 1973,-1133.5 1973,-523.5 ; 3240,-726.83 3240,-523.5 ; 4080,-726.83 4080,-523.5 ; 4702,-1140 4702,-937.17
  text "ALL ARTWORK VIEWED FROM TOP SIDE" at -428.5,-655.67 h60
  text "BOARD #:" at 2048,-655.67 h60
  text ".PRJ_Number" at 2593.5,-655.67 h60
  text "REV:" at 3438,-655.67 h60
  text ".PCB_Rev" at 3729.5,-655.67 h60
  text "SVN REV:" at 4276,-655.67 h60
  text ".VersionControl_RevNumber" at 4782,-655.67 h60
  text "LAYER NAME =" at -428.5,-858.49 h60
  text "PLOT NAME =" at -428.5,-1064.34 h60
  text ".plot_File_Name" at 377,-1064.34 h60
  text "GENERATED    :" at 2050,-1064.34 h60
  text ".Print_Date" at 2919.5,-1064.34 h60
  text ".Print_Time" at 3648.5,-1064.34 h60
  text "TEXAS INSTRUMENTS" at 4913,-1064.34 h60
M12 Stackup:
  drawing of 399 lines, arcs and shapes, not listed
  text "Layer" at 9628.7,7847.5 h60
  text "Name" at 10038.61,7847.5 h60
  text "Material" at 10968.35,7847.5 h60
  text "Thickness" at 11828.12,7847.5 h60
  text "Constant" at 12477.96,7847.5 h60
  text "Board Layer Stack" at 13047.82,7847.5 h60
  text "1" at 9628.7,7727.5 h60
  text "Top Overlay" at 10038.61,7727.5 h60
  text "2" at 9628.7,7607.5 h60
  text "Top Solder" at 10038.61,7607.5 h60
  text "Solder Resist" at 10968.35,7607.5 h60
  text "0.40mil" at 11828.12,7607.5 h60
  text "3.5" at 12477.96,7607.5 h60
  text "3" at 9628.7,7487.5 h60
  text "Top Layer" at 10038.61,7487.5 h60
  text "Copper" at 10968.35,7487.5 h60
  text "2.80mil" at 11828.12,7487.5 h60
  text "4" at 9628.7,7367.5 h60
  text "Dielectric1" at 10038.61,7367.5 h60
  text "FR-4" at 10968.35,7367.5 h60
  text "8.00mil" at 11828.12,7367.5 h60
  text "4.2" at 12477.96,7367.5 h60
  text "5" at 9628.7,7247.5 h60
  text "MidLayer1" at 10038.61,7247.5 h60
  text "Copper" at 10968.35,7247.5 h60
  text "2.80mil" at 11828.12,7247.5 h60
  text "6" at 9628.7,7127.5 h60
  text "Dielectric2" at 10038.61,7127.5 h60
  text "FR-4" at 10968.35,7127.5 h60
  text "8.00mil" at 11828.12,7127.5 h60
  text "4.8" at 12477.96,7127.5 h60
  text "7" at 9628.7,7007.5 h60
  text "MidLayer2" at 10038.61,7007.5 h60
  text "Copper" at 10968.35,7007.5 h60
  text "2.80mil" at 11828.12,7007.5 h60
  text "8" at 9628.7,6887.5 h60
  text "Dielectric3" at 10038.61,6887.5 h60
  text "FR-4" at 10968.35,6887.5 h60
  text "12.00mil" at 11828.12,6887.5 h60
  text "4.2" at 12477.96,6887.5 h60
  text "9" at 9628.7,6767.5 h60
  text "MidLayer3" at 10038.61,6767.5 h60
  text "Copper" at 10968.35,6767.5 h60
  text "2.80mil" at 11828.12,6767.5 h60
  text "10" at 9628.7,6647.5 h60
  text "Dielectric4" at 10038.61,6647.5 h60
  text "FR-4" at 10968.35,6647.5 h60
  text "8.00mil" at 11828.12,6647.5 h60
  text "4.8" at 12477.96,6647.5 h60
  text "11" at 9628.7,6527.5 h60
  text "MidLayer4" at 10038.61,6527.5 h60
  text "Copper" at 10968.35,6527.5 h60
  text "2.80mil" at 11828.12,6527.5 h60
  text "12" at 9628.7,6407.5 h60
  text "Dielectric5" at 10038.61,6407.5 h60
  text "FR-4" at 10968.35,6407.5 h60
  text "8.00mil" at 11828.12,6407.5 h60
  text "4.8" at 12477.96,6407.5 h60
  text "13" at 9628.7,6287.5 h60
  text "Bottom Layer" at 10038.61,6287.5 h60
  text "Copper" at 10968.35,6287.5 h60
  text "2.80mil" at 11828.12,6287.5 h60
  text "14" at 9628.7,6167.5 h60
  text "Bottom Solder" at 10038.61,6167.5 h60
  text "Solder Resist" at 10968.35,6167.5 h60
  text "0.40mil" at 11828.12,6167.5 h60
  text "3.5" at 12477.96,6167.5 h60
  text "15" at 9628.7,6047.5 h60
  text "Bottom Overlay" at 10038.61,6047.5 h60
  text ".Layer_Name" at 377,-858.49 h60
M13 Component Bodies Top:
  text ".Layer_Name" at 377,-858.49 h60
M14 Component Bodies Bottom:
  text ".Layer_Name" at 377,-858.49 h60
M15 Courtyards Top:
  text ".Layer_Name" at 377,-858.49 h60
M16 Courtyards Bottom:
  text ".Layer_Name" at 377,-858.49 h60
Drill Drawing:
  lines w10: 6069.41,2525 6069.41,2541.67 6086.08,2558.33 6069.41,2575 6069.41,2591.67 6086.08,2591.67 6102.74,2575 6119.41,2591.67 6136.08,2591.67 6136.08,2575 6119.41,2558.33 6136.08,2541.67 6136.08,2525 6119.41,2525 6102.74,2541.67 6086.08,2525 6069.41,2525 ; 6069.41,2858.33 6102.74,2825 6136.08,2858.33 6102.74,2891.67 6069.41,2858.33 ; 6069.41,2975 6102.74,2991.67 6136.08,2975 6119.41,3008.33 6136.08,3041.67 6102.74,3025 6069.41,3041.67 6086.08,3008.33 6069.41,2975 ; 6069.41,3141.67 6086.08,3141.67 6086.08,3125 6119.41,3125 6119.41,3141.67 6136.08,3141.67 6136.08,3175 6119.41,3175 6119.41,3191.67 6086.08,3191.67 6086.08,3175 6069.41,3175 6069.41,3141.67 ; 6069.41,3291.67 6086.08,3291.67 6102.74,3275 6119.41,3291.67 6136.08,3291.67 6119.41,3308.33 6136.08,3325 6119.41,3325 6102.74,3341.67 6086.08,3325 6069.41,3325 6086.08,3308.33 6069.41,3291.67 ; 6069.41,3491.67 6136.08,3491.67 6102.74,3425 6069.41,3491.67 ; 6082.74,2538.33 6082.74,2548.33 6092.74,2558.33 6082.74,2568.33 6082.74,2578.33 6092.74,2578.33 6102.74,2568.33 6112.74,2578.33 6122.74,2578.33 6122.74,2568.33 6112.74,2558.33 6122.74,2548.33 6122.74,2538.33 6112.74,2538.33 6102.74,2548.33 6092.74,2538.33 6082.74,2538.33 ; 6082.74,2988.33 6102.74,2998.33 6122.74,2988.33 6112.74,3008.33 6122.74,3028.33 6102.74,3018.33 6082.74,3028.33 6092.74,3008.33 6082.74,2988.33 ; 6082.74,3148.33 6092.74,3148.33 6092.74,3138.33 6112.74,3138.33 6112.74,3148.33 6122.74,3148.33 6122.74,3168.33 6112.74,3168.33 6112.74,3178.33 6092.74,3178.33 6092.74,3168.33 6082.74,3168.33 6082.74,3148.33 ; 6082.74,3298.33 6092.74,3298.33 6102.74,3288.33 6112.74,3298.33 6122.74,3298.33 6112.74,3308.33 6122.74,3318.33 6112.74,3318.33 6102.74,3328.33 6092.74,3318.33 6082.74,3318.33 6092.74,3308.33 6082.74,3298.33 ; 6082.74,3478.33 6122.74,3478.33 6102.74,3438.33 6082.74,3478.33
  lines w15: 6009.62,2480 9584.68,2480 ; 6009.62,3530 9584.68,3530 ; 6560.49,2330 6560.49,3680 ; 7150.34,2330 7150.34,3680 ; 8300,2330 8300,3680 ; 8805.88,2330 8805.88,3680 ; 6009.62,2330 9584.68,2330 9584.68,3680 6009.62,3680 6009.62,2330
  text "Symbol" at 6099.62,3575 h72
  text "Count" at 6605.49,3575 h72
  text "Hole Size" at 7195.34,3575 h72
  text "Plated" at 8345,3575 h72
  text "Hole Type" at 8850.88,3575 h72
  text "21" at 6605.49,3425 h60
  text "7.87mil (0.200mm)" at 7195.34,3425 h60
  text "PTH" at 8345,3425 h60
  text "Round" at 8850.88,3425 h60
  text "393" at 6605.49,3275 h60
  text "10.00mil (0.254mm)" at 7195.34,3275 h60
  text "PTH" at 8345,3275 h60
  text "Round" at 8850.88,3275 h60
  text "19" at 6605.49,3125 h60
  text "14.00mil (0.356mm)" at 7195.34,3125 h60
  text "PTH" at 8345,3125 h60
  text "Round" at 8850.88,3125 h60
  text "3" at 6605.49,2975 h60
  text "24.00mil (0.610mm)" at 7195.34,2975 h60
  text "PTH" at 8345,2975 h60
  text "Round" at 8850.88,2975 h60
  text "7" at 6605.49,2825 h60
  text "63.00mil (1.600mm)" at 7195.34,2825 h60
  text "PTH" at 8345,2825 h60
  text "Round" at 8850.88,2825 h60
  text "4" at 6605.49,2675 h60
  text "159.00mil (4.039mm)" at 7195.34,2675 h60
  text "NPTH" at 8345,2675 h60
  text "Round" at 8850.88,2675 h60
  text "A" at 6070.53,2665.01 h66.67
  text "4" at 6605.49,2525 h60
  text "214.57mil (5.450mm)" at 7195.34,2525 h60
  text "PTH" at 8345,2525 h60
  text "Round" at 8850.88,2525 h60
  text "451 Total" at 6605.49,2375 h60
  text ".Layer_Name" at 377,-858.49 h60

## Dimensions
-200,-410.5 to 800,-410.5 on M2 Board Dimensions
0,0 to 3650,0 on M2 Board Dimensions
0,0 to 0,3650 on M2 Board Dimensions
